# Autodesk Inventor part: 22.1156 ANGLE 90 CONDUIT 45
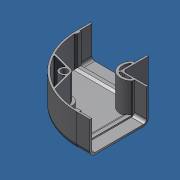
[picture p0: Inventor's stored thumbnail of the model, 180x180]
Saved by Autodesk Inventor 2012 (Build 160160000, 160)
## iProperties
Created: 2014-05
Part Number: 22.1156 ANGLE 90 CONDUIT 45
Material: ABS Plastic
Document SubType Name: Modeling
Designer: Admin
Density: 1.06 g/cm^3
Mass: 16.0015 g
Surface Area: 192.617 cm^2
Volume: 15.0958 cm^3
Art.-Nr.: 22.1156/0
L: -
Stück: 1
5: Winkel 90°  für Kabelkanal 45
7: 22.1156/0
8: MiniTec Maschinenbau GmbH & Co KG
Author: Admin
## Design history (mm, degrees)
feature "Base1"
body "Solid1"
